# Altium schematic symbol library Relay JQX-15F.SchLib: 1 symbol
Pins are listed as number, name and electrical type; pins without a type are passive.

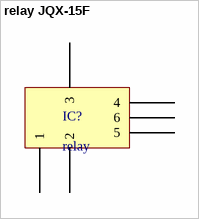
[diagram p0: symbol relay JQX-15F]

## relay JQX-15F
designator IC?, comment relay
footprint relay JQX 15F
pins: 1, 2, 3, 4, 5, 6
